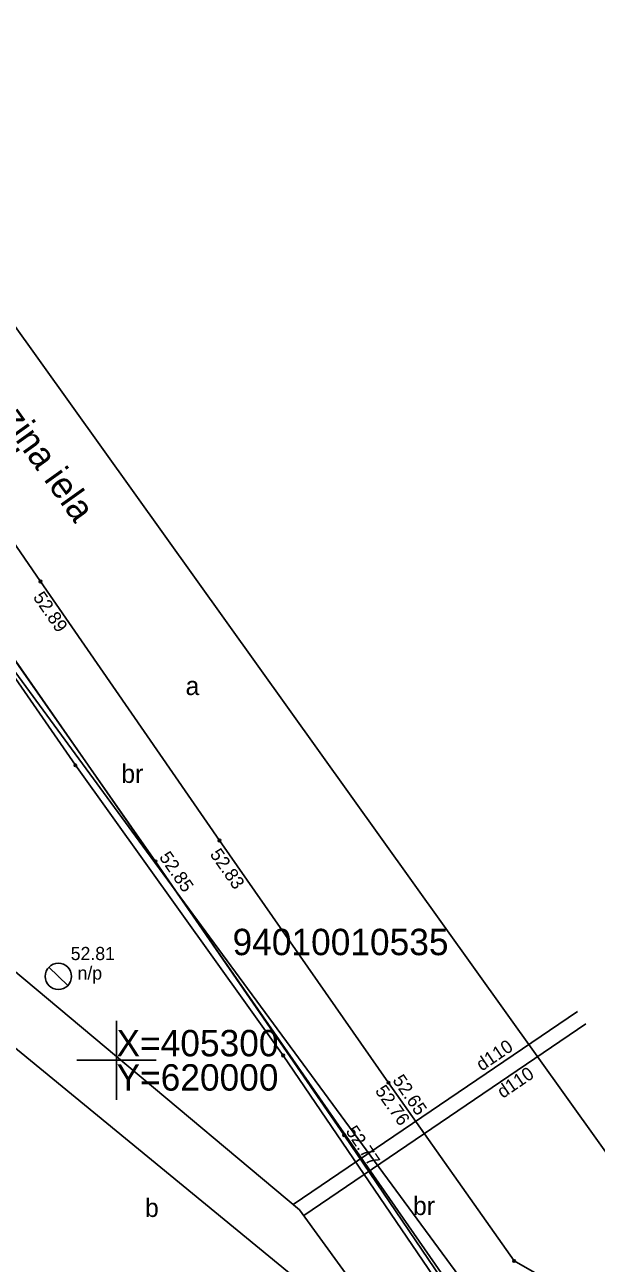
# Model space of a CAD drawing. Extents: x 619806 to 620082, y 405176 to 405386.
# Drawn here: x 619996.52 to 620018.17, y 405292.31 to 405339.23 of the extents above; entities that cross this region are included whole.
import ezdxf

# ---------------------------------------------------------------- set-up
doc = ezdxf.new("R2010")
doc.units = 0
for name, color, linetype in [('APGR_SARK_####_####_#', 7, 'Continuous'), ('APGS_VADP_ZSPR_####_#', 7, 'Continuous'), ('CELI_CAPM_####_####_#', 7, 'Continuous'), ('CELI_CSEG_####_TKST_#', 7, 'Continuous'), ('CELI_IELA_####_TKST_#', 7, 'Continuous'), ('CELI_SEGL_####_####_#', 7, 'Continuous'), ('CKOM_ELEM_####_####_#', 7, 'Continuous'), ('CKOM_ELEM_####_TKST_#', 7, 'Continuous'), ('GEOD_ELEM_####_####_#', 7, 'Continuous'), ('GEOD_KORD_####_TKST_#', 7, 'Continuous'), ('RAMI_UZMR_####_####_#', 7, 'Continuous'), ('RELJ_AATZ_####_TKST_#', 7, 'Continuous'), ('RELJ_ELEM_####_####_#', 7, 'Continuous'), ('ROBZ_PROJ_####_TKST_#', 7, 'Continuous'), ('ROBZ_UZMR_####_####_#', 7, 'Continuous'), ('SAKT_VADP_KABE_####_#', 7, 'Continuous'), ('UDTK_VADP_UDEN_####_#', 7, 'Continuous'), ('UDTK_VADP_UDEN_TKST_#', 7, 'Continuous')]:
    doc.layers.add(name, color=color, linetype=linetype)

msp = doc.modelspace()

# ---------------------------------------------------------------- linework, layer by layer
at = {"layer": 'APGR_SARK_####_####_#'}
msp.add_lwpolyline([(619976.198, 405343.424), (619987.786, 405326.116), (620001.138, 405307.928), (620014.265, 405290.061), (620015.405, 405288.784), (620016.767, 405287.746), (620041.487, 405272.379), (619990.053, 405197.403), (619990.053, 405197.403)], dxfattribs=at)
at = {"layer": 'APGS_VADP_ZSPR_####_#'}
msp.add_lwpolyline([(619990.647, 405321.492), (619992.044, 405320.41), (619998.442, 405311.177), (620006.316, 405300.184), (620012.827, 405290.604), (620013.926, 405290.046), (620013.66, 405289.472), (620014.139, 405289.916), (620020.167, 405285.36), (620029.979, 405279.119), (620034.093, 405276.637), (620034.718, 405277.157), (620034.581, 405276.433), (620041.718, 405272.423), (620046.265, 405269.109)], dxfattribs=at)
at = {"layer": 'CELI_CAPM_####_####_#'}
msp.add_lwpolyline([(619965.216, 405366.112), (619969.788, 405359.459), (619973.297, 405354.436), (619974.566, 405352.6), (619974.617, 405350.85), (619979.181, 405344.059), (619986.049, 405334.146), (619993.139, 405323.923), (619997.124, 405318.139), (620003.902, 405308.323), (620010.301, 405299.151), (620015.066, 405292.395), (620017.489, 405291.013)], dxfattribs=at)
at = {"layer": 'CELI_SEGL_####_####_#'}
msp.add_lwpolyline([(620013.524, 405289.938), (620008.624, 405297.164), (620001.476, 405307.535), (619994.548, 405317.437), (619991.854, 405321.355)], dxfattribs=at)
at = {"layer": 'CKOM_ELEM_####_####_#'}
for p, q in [((619997.437, 405303.528), (619998.155, 405302.832)), ((619997.796, 405303.18), (619997.795, 405303.179))]:
    msp.add_line(p, q, dxfattribs=at)
msp.add_circle((619997.796, 405303.18), 0.5, dxfattribs=at)
at = {"layer": 'GEOD_ELEM_####_####_#'}
for p, q in [((620000, 405301.5), (620000, 405300)), ((619998.5, 405300), (620000, 405300)), ((620000, 405300), (620000, 405298.5)), ((620000, 405300), (620001.5, 405300))]:
    msp.add_line(p, q, dxfattribs=at)
at = {"layer": 'RAMI_UZMR_####_####_#'}
msp.add_lwpolyline([(619874.687, 405324.979), (619926.719, 405349.544), (619966.669, 405369.042), (620021.738, 405292.03), (620049.703, 405275.476), (620026.189, 405242.287), (620012.147, 405222.917), (619996.603, 405200.928), (619989.997, 405199.173), (619982.328, 405199.155), (619922.669, 405233.014), (619882.137, 405255.756), (619859.084, 405268.056), (619820.646, 405290.715), (619813.744, 405295.206), (619820.645, 405298.752)], close=True, dxfattribs=at)
at = {"layer": 'RELJ_ELEM_####_####_#'}
for centre in [(619997.124, 405318.139), (619998.442, 405311.177), (620003.902, 405308.323), (620001.476, 405307.535), (620006.316, 405300.184), (620010.301, 405299.151), (620008.624, 405297.164), (620015.066, 405292.395)]:
    msp.add_circle(centre, 0.05, dxfattribs=at)
at = {"layer": 'ROBZ_UZMR_####_####_#'}
msp.add_line((619991.921, 405321.247), (620012.847, 405291.155), dxfattribs=at)
at = {"layer": 'SAKT_VADP_KABE_####_#'}
msp.add_lwpolyline([(619935.629, 405357.201), (619939.538, 405347.363), (619973.032, 405319.457), (620006.975, 405291.595), (620036.262, 405267.248), (620043.553, 405261.241)], dxfattribs=at)
at = {"layer": 'UDTK_VADP_UDEN_####_#'}
for points in [[(619945.834, 405355.555), (619951.504, 405344.209), (619959.966, 405336.395), (619975.103, 405321.007), (620000.001, 405300.143)], [(620006.686, 405294.541), (620017.461, 405301.846)], [(620007.092, 405294.117), (620017.774, 405301.384)], [(619999.999, 405300.145), (620006.936, 405294.332)], [(620006.936, 405294.332), (620021.003, 405274.963), (620032.468, 405267.412)]]:
    msp.add_lwpolyline(points, dxfattribs=at)

# ---------------------------------------------------------------- texts
at = {"layer": 'CELI_CSEG_####_TKST_#'}
for s, p in [('a', (620002.615, 405313.836)), ('br', (620000.183, 405310.508)), ('b', (620001.08, 405294.063)), ('br', (620011.231, 405294.135))]:
    msp.add_text(s, height=0.7, dxfattribs=at).set_placement(p)
at = {"layer": 'CELI_IELA_####_TKST_#'}
msp.add_text('Emīla Dārziņa iela', height=1, rotation=305.5671, dxfattribs=at).set_placement((619992.123, 405329.138))
at = {"layer": 'CKOM_ELEM_####_TKST_#'}
for s, p in [('52.81', (619998.266, 405303.795)), ('n/p', (619998.524, 405303.055))]:
    msp.add_text(s, height=0.5, dxfattribs=at).set_placement(p)
at = {"layer": 'GEOD_KORD_####_TKST_#'}
for s, p in [('X=405300', (620000, 405300.15)), ('Y=620000', (620000, 405298.85))]:
    msp.add_text(s, height=1, dxfattribs=at).set_placement(p)
at = {"layer": 'RELJ_AATZ_####_TKST_#'}
for s, rotation, p in [(' 52.89', 304.6253, (619996.713, 405317.693)), (' 52.85', 304.5758, (620001.491, 405307.848)), (' 52.83', 304.9022, (620003.411, 405307.956)), (' 52.65', 304.5329, (620010.33, 405299.396)), (' 52.76', 305.1953, (620009.665, 405298.993)), (' 52.77', 304.1415, (620008.558, 405297.464))]:
    msp.add_text(s, height=0.5, rotation=rotation, dxfattribs=at).set_placement(p)
at = {"layer": 'ROBZ_PROJ_####_TKST_#'}
msp.add_text('94010010535', height=1, dxfattribs=at).set_placement((620004.395, 405303.982))
at = {"layer": 'UDTK_VADP_UDEN_TKST_#'}
for rotation, p in [(34.1368, (620013.837, 405299.57)), (34.2273, (620014.632, 405298.536))]:
    msp.add_text('d110', height=0.5, rotation=rotation, dxfattribs=at).set_placement(p)

doc.saveas('drawing.dxf')
